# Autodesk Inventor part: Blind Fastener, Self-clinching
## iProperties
Title: Blind Fastener, Self-clinching
Author: H Gwin
Created: 2002-03
Part Number: PEM, B-832-2
Material: Steel, High Strength Low Alloy
Description: Blind Fastener, 8-32, Mat'l >.056 Thk
Document SubType Name: Modeling
Designer: H Gwin
Control State: 0
Master: False
Checked Out: False
Last Check In By: halg
Last Check In Date: 2002-03-07
PropertySet Name: Design Tracking Control
Shininess: 20.0
Length Units: 11272
Angle Units: 11286
Time Units: 11279
Mass Units: 11290
Length Display Precision: 3
Angle Display Precision: 2
Compacted: True
PropertySet Name: _Private Model Information
Density: 7.839999999999999
Volumn: 0.09135232014549177
Area: 2.6024304262235907
PropertySet Name: Model Information
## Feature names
1. Revolution1
2. Chamfer1
